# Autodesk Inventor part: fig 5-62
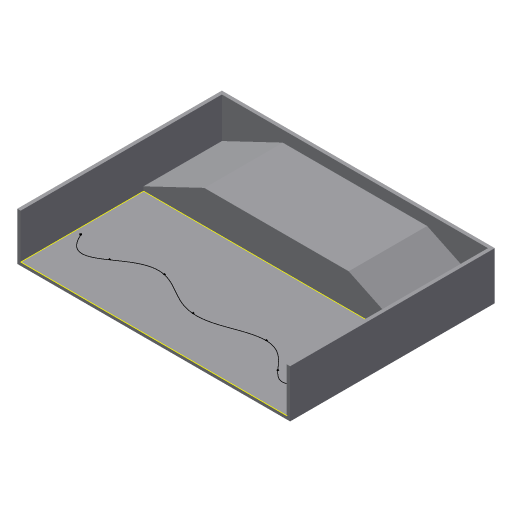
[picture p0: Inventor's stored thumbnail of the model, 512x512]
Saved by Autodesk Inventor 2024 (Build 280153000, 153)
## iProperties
Created: 2004-05
Part Number: fig 5-62
Document SubType Name: Modeling
Designer: CADCIM Technologies
Manufacturer: Standard
Standards Organization: Custom
Density: 1 g/cm^3
Material: Generic
Appearance: Default
Author: CADCIM Technologies
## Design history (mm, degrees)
sketch "Sketch1"
  geometry: L1 (-40, -30)-(40, -30); L2 (40, -30)-(40, 30); L3 (40, 30)-(-40, 30); L4 (-40, 30)-(-40, -30); 1 further point
  constraints: 8 end point, 2 parallel, 1 horizontal, 1 perpendicular, 1 other
  dimensions: "d0" = 80 distance of L1.start L1.end; "d1" = 60 distance of L3.end L1.start; "d2" = 30 distance from line of point (0, 0) L1; "d3" = 40 distance from line of point (0, 0) L4
extrude "Extrusion1" new body sketch "Sketch1" distance "d4" = 14; taper "d5" = 0 deg
shell "Shell1" dims "d6" = 1
workplane "Work Plane1"
sketch "Sketch2"
  geometry: L1 (78, -13)-(78, -11.813); L2 (0, -11.813)-(0, -13); L3 (0, -13)-(78, -13); L4 (0, -11.813)-(17.826, -3.295); L5 (17.826, -3.295)-(60.174, -3.295); L6 (60.174, -3.295)-(78, -11.813); L7 (79, -13.795)-(78, -13.795); L8 (78, 0)-(78, -13) reference; L9 (0, -13)-(0, 0) reference; L10 (78, -13)-(0, -13) reference
  constraints: 14 end point, 3 collinear, 2 equal length, 2 vertical, 1 horizontal alignment, 1 parallel, 1 point on line
extrude "Extrusion2" join sketch "Sketch2" stored distance "d8" = 14; taper "d9" = 0 deg
workplane "Work Plane2"
sketch "Sketch4"
  geometry: L1 (78, 36)-(0, 36) reference; L2 (0, 36)-(0, 0) reference; L3 (78, 0)-(0, 0) reference; L4 (78, 0)-(78, 36) reference; 7 further points
  constraints: 7 other
body "Solid1"
other parameters: "d7" = 23, "d18" = 4
